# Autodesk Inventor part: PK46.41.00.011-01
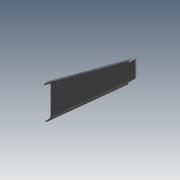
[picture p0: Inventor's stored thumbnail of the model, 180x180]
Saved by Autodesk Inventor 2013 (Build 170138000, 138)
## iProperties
Created: 2005-07
Part Number: PK46.41.00.011-01
Material: Steel, Mild
Document SubType Name: Листовой материал
Designer: PVitaliy
Manufacturer: Standard
Standards Organization: Custom
Density: 7.86 g/cm^3
Mass: 1058.63 g
Surface Area: 929.402 cm^2
Volume: 134.686 cm^3
Author: PVitaliy
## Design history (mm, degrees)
derived "PK46.41.00.113.ipt"
body "Solid1"
tag "TaggingFeature2"
feature "DerivedBody::PK46.41.00.113.ipt" dims "d0" = 10
